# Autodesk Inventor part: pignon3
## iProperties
Author: Administrateur
Shininess: 20.0
PropertySet Name: _Private Model Information
Length Units: 11269
Angle Units: 11283
Time Units: 11279
Mass Units: 11290
Length Display Precision: 3
Angle Display Precision: 2
Compacted: False
Created: 2001-04
Part Number: pignon3
Material: Par défaut
Document SubType Name: Modélisation
Designer: Administrateur
Control State: 0
Master: False
Checked Out: False
PropertySet Name: Design Tracking Control
Density: 0.0
Volumn: 0.0
Area: 0.0
PropertySet Name: Model Information
